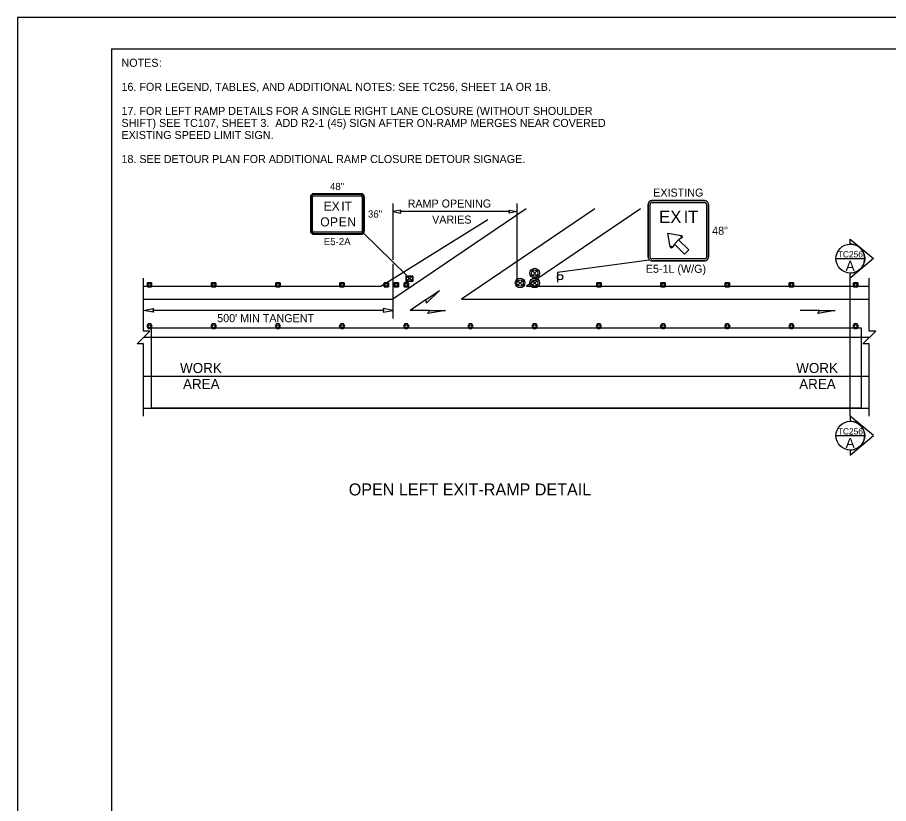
# Model space of a CAD drawing. Extents: x 99999 to 100116, y 99995 to 100013.
# Drawn here: x 100079.06 to 100087.75, y 100002.85 to 100010.69 of the extents above; entities that cross this region are included whole.
import ezdxf

# ---------------------------------------------------------------- set-up
doc = ezdxf.new("R2010")
doc.units = 0
for name, color, linetype in [('RD_MK_LineEdgeYellow', 7, 'Continuous'), ('RD_MK_LineLane', 7, 'Continuous'), ('SH_DE_DetailHeading2Text', 7, 'Continuous'), ('SH_GI_GeneralNotesBodyText', 7, 'Continuous'), ('SH_GI_PlotLimits', 7, 'Continuous'), ('SH_GI_SectionCut', 7, 'Continuous'), ('SH_GI_SheetBorder', 7, 'Continuous'), ('TR_SN_ConstructionSigns', 7, 'Continuous'), ('TR_WZ_PortableSignMount5ftMinBlk-Org', 7, 'Continuous'), ('TR_WZ_TallChanDevice', 7, 'Continuous'), ('TR_WZ_TrafficCone', 7, 'Continuous'), ('TR_WZ_TrafficSafetyDrum', 7, 'Continuous'), ('TR_WZ_WorkAreaLabel', 7, 'Continuous'), ('TR_WZ_WorkZoneDetails', 7, 'Continuous'), ('TR_WZ_WorkZoneTextCurrent', 7, 'Continuous')]:
    doc.layers.add(name, color=color, linetype=linetype)

msp = doc.modelspace()

# ---------------------------------------------------------------- linework, layer by layer
at = {"layer": 'RD_MK_LineEdgeYellow'}
for p, q in [((100084.1333, 100008.7784), (100082.8064, 100007.8789)), ((100080.32, 100007.8789), (100082.8064, 100007.8789)), ((100084.1377, 100007.8789), (100087.555, 100007.8789)), ((100080.32, 100007.1109), (100087.555, 100007.1109))]:
    msp.add_line(p, q, dxfattribs=at)
at = {"layer": 'RD_MK_LineLane'}
msp.add_lwpolyline([(100087.555, 100007.4949), (100080.32, 100007.4949)], dxfattribs=at)
at = {"layer": 'SH_GI_PlotLimits'}
msp.add_lwpolyline([(100079.0625, 99999.6875), (100096.0625, 99999.6875), (100096.0625, 100010.6875), (100079.0625, 100010.6875)], close=True, dxfattribs=at)
at = {"layer": 'SH_GI_SectionCut'}
for p, q in [((100087.3657, 100008.4258), (100087.3657, 100008.4767)), ((100087.3657, 100008.4767), (100087.5983, 100008.2818)), ((100087.5983, 100008.2818), (100087.3657, 100008.0869)), ((100087.3657, 100008.0869), (100087.3657, 100008.1378)), ((100087.3657, 100006.7109), (100087.3657, 100008.0869)), ((100087.3657, 100006.7109), (100087.3657, 100006.66)), ((100087.5983, 100006.516), (100087.3657, 100006.7109)), ((100087.3657, 100006.3211), (100087.5983, 100006.516)), ((100087.3657, 100006.372), (100087.3657, 100006.3211))]:
    msp.add_line(p, q, dxfattribs=at)
for points in [[(100087.2217, 100008.2818), (100087.5097, 100008.2818)], [(100087.2217, 100006.516), (100087.5097, 100006.516)]]:
    msp.add_lwpolyline(points, dxfattribs=at)
for centre in [(100087.3657, 100008.2818), (100087.3657, 100006.516)]:
    msp.add_circle(centre, 0.144, dxfattribs=at)
for centre in [(100087.3657, 100008.2818), (100087.3657, 100006.516)]:
    msp.add_arc(centre, 0.144, 269.99779, 90.00221, dxfattribs=at)
at = {"layer": 'SH_GI_SheetBorder'}
for q in [(100080, 100000), (100095.75, 100010.375)]:
    msp.add_line((100080, 100010.375), q, dxfattribs=at)
at = {"layer": 'TR_SN_ConstructionSigns'}
for p, q in [((100081.983, 100008.8955), (100081.983, 100008.558)), ((100081.9914, 100008.8955), (100081.9914, 100008.558)), ((100082.0055, 100008.558), (100082.0055, 100008.8955)), ((100082.4893, 100008.9292), (100082.0168, 100008.9292)), ((100082.4893, 100008.9208), (100082.0168, 100008.9208)), ((100082.0168, 100008.9067), (100082.4893, 100008.9067)), ((100082.5005, 100008.8955), (100082.5005, 100008.558)), ((100082.5146, 100008.558), (100082.5146, 100008.8955)), ((100082.523, 100008.558), (100082.523, 100008.8955)), ((100085.3881, 100008.8603), (100085.9131, 100008.8603)), ((100085.9131, 100008.8603), (100085.3881, 100008.8603)), ((100085.9131, 100008.8603), (100085.3881, 100008.8603)), ((100085.9131, 100008.8603), (100085.3881, 100008.8603)), ((100085.9131, 100008.8603), (100085.3881, 100008.8603)), ((100085.9131, 100008.8603), (100085.9131, 100008.8603)), ((100085.3506, 100008.2978), (100085.3506, 100008.8228)), ((100085.3506, 100008.8228), (100085.3506, 100008.8228)), ((100085.3506, 100008.8228), (100085.3506, 100008.2978)), ((100085.3506, 100008.8228), (100085.3506, 100008.2978)), ((100085.3506, 100008.8228), (100085.3506, 100008.2978)), ((100085.3506, 100008.8228), (100085.3506, 100008.2978)), ((100085.3693, 100008.2978), (100085.3693, 100008.8228)), ((100085.3881, 100008.8416), (100085.9131, 100008.8416)), ((100085.9318, 100008.8228), (100085.9318, 100008.2978)), ((100085.9506, 100008.8228), (100085.9506, 100008.2978)), ((100085.9506, 100008.2978), (100085.9506, 100008.8228)), ((100085.9506, 100008.2978), (100085.9506, 100008.8228)), ((100085.9506, 100008.2978), (100085.9506, 100008.8228)), ((100085.9506, 100008.2978), (100085.9506, 100008.8228)), ((100082.4893, 100008.5467), (100082.0168, 100008.5467)), ((100082.0168, 100008.5327), (100082.4893, 100008.5327)), ((100082.0168, 100008.5242), (100082.4893, 100008.5242)), ((100085.5462, 100008.5358), (100085.6821, 100008.511)), ((100085.571, 100008.3999), (100085.5462, 100008.5358)), ((100085.6821, 100008.511), (100085.6793, 100008.4988)), ((100085.6793, 100008.4988), (100085.6821, 100008.511)), ((100085.6793, 100008.4988), (100085.6857, 100008.4881)), ((100085.6857, 100008.4881), (100085.6793, 100008.4988)), ((100085.6125, 100008.4275), (100085.5939, 100008.3963)), ((100085.6125, 100008.4275), (100085.6544, 100008.4695)), ((100085.6544, 100008.4695), (100085.6125, 100008.4275)), ((100085.713, 100008.327), (100085.6125, 100008.4275)), ((100085.6857, 100008.4881), (100085.6544, 100008.4695)), ((100085.6544, 100008.4695), (100085.755, 100008.369)), ((100085.5832, 100008.4027), (100085.571, 100008.3999)), ((100085.571, 100008.3999), (100085.5832, 100008.4027)), ((100085.5939, 100008.3963), (100085.5832, 100008.4027)), ((100085.5832, 100008.4027), (100085.5939, 100008.3963)), ((100085.755, 100008.369), (100085.713, 100008.327)), ((100085.9131, 100008.2791), (100085.3881, 100008.2791)), ((100085.9131, 100008.2603), (100085.3881, 100008.2603)), ((100085.3881, 100008.2603), (100085.3881, 100008.2603)), ((100085.3881, 100008.2603), (100085.9131, 100008.2603)), ((100085.3881, 100008.2603), (100085.9131, 100008.2603)), ((100085.3881, 100008.2603), (100085.9131, 100008.2603)), ((100085.9506, 100008.2978), (100085.9506, 100008.2978))]:
    msp.add_line(p, q, dxfattribs=at)
for points in [[(100085.3881, 100008.2603), (100085.3881, 100008.2603)], [(100085.3881, 100008.2603), (100085.9131, 100008.2603), (100085.9131, 100008.2603)]]:
    msp.add_lwpolyline(points, dxfattribs=at)
for centre, radius, start, end in [((100082.0168, 100008.8955), 0.0338, 90, 180), ((100082.0168, 100008.8955), 0.0253, 90, 180.00001), ((100082.0168, 100008.8955), 0.0112, 90, 180.00001), ((100082.4893, 100008.8955), 0.0338, 360, 90), ((100082.4893, 100008.8955), 0.0253, 360, 90), ((100082.4893, 100008.8955), 0.0112, 360, 90), ((100085.3881, 100008.8228), 0.0375, 90, 180.00001), ((100085.3881, 100008.8228), 0.0375, 90, 180), ((100085.3881, 100008.8228), 0.0375, 90, 180), ((100085.3881, 100008.8228), 0.0375, 90, 180), ((100085.3881, 100008.8228), 0.0375, 90, 180), ((100085.9131, 100008.8228), 0.0375, 0, 90), ((100085.9131, 100008.8228), 0.0375, 0, 90), ((100085.9131, 100008.8228), 0.0375, 0, 90), ((100085.9131, 100008.8228), 0.0375, 0, 90), ((100085.9131, 100008.8228), 0.0375, 0, 90), ((100085.3881, 100008.8228), 0.0187, 90, 180.00001), ((100085.9131, 100008.8228), 0.0187, 0, 90), ((100082.0168, 100008.558), 0.0338, 180, 270.00001), ((100082.0168, 100008.558), 0.0253, 180.00001, 270), ((100082.0168, 100008.558), 0.0112, 180.00001, 270), ((100082.4893, 100008.558), 0.0338, 270.00001, 0.00001), ((100082.4893, 100008.558), 0.0253, 270, 0.00001), ((100082.4893, 100008.558), 0.0112, 270, 0.00001), ((100085.6793, 100008.4988), 0.0125, 300.67412, 77.22876), ((100085.5832, 100008.4027), 0.0125, 192.77123, 329.32586), ((100085.3881, 100008.2978), 0.0375, 180.00001, 270), ((100085.3881, 100008.2978), 0.0375, 180, 270.00001), ((100085.3881, 100008.2978), 0.0375, 180, 270.00001), ((100085.3881, 100008.2978), 0.0375, 180, 270), ((100085.3881, 100008.2978), 0.0375, 180, 270.00001), ((100085.3881, 100008.2978), 0.0187, 180.00001, 270), ((100085.9131, 100008.2978), 0.0375, 270, 0.00001), ((100085.9131, 100008.2978), 0.0375, 270.00001, 0.00001), ((100085.9131, 100008.2978), 0.0375, 270.00001, 0.00001), ((100085.9131, 100008.2978), 0.0375, 270.00001, 0.00001), ((100085.9131, 100008.2978), 0.0187, 270, 0.00001), ((100085.9131, 100008.2978), 0.0375, 270.00001, 0.00001)]:
    msp.add_arc(centre, radius, start, end, dxfattribs=at)
at = {"layer": 'TR_WZ_PortableSignMount5ftMinBlk-Org'}
for p, q in [((100082.9389, 100008.0416), (100082.9389, 100008.1216)), ((100083.0056, 100008.1076), (100082.9389, 100008.0556)), ((100083.0056, 100008.0556), (100082.9389, 100008.1076)), ((100082.9723, 100008.0816), (100082.9723, 100008.0816)), ((100082.9724, 100008.0816), (100082.9724, 100008.0816))]:
    msp.add_line(p, q, dxfattribs=at)
for points in [[(100083.0056, 100008.1076), (100083.0056, 100008.0556), (100082.9389, 100008.0556), (100082.9389, 100008.1076)], [(100082.9389, 100008.0556), (100083.0056, 100008.0556), (100083.0056, 100008.1076), (100082.9389, 100008.1076)]]:
    msp.add_lwpolyline(points, close=True, dxfattribs=at)
at = {"layer": 'TR_WZ_TallChanDevice'}
for points in [[(100080.3928, 100007.6319), (100080.3651, 100007.6319), (100080.3512, 100007.6079), (100080.3651, 100007.5839), (100080.3928, 100007.5839), (100080.4066, 100007.6079)], [(100081.0328, 100007.6319), (100081.0051, 100007.6319), (100080.9912, 100007.6079), (100081.0051, 100007.5839), (100081.0328, 100007.5839), (100081.0466, 100007.6079)], [(100081.6728, 100007.6319), (100081.6451, 100007.6319), (100081.6312, 100007.6079), (100081.6451, 100007.5839), (100081.6728, 100007.5839), (100081.6866, 100007.6079)], [(100082.3128, 100007.6319), (100082.2851, 100007.6319), (100082.2712, 100007.6079), (100082.2851, 100007.5839), (100082.3128, 100007.5839), (100082.3266, 100007.6079)], [(100082.9528, 100007.6319), (100082.9251, 100007.6319), (100082.9112, 100007.6079), (100082.9251, 100007.5839), (100082.9528, 100007.5839), (100082.9666, 100007.6079)], [(100083.5928, 100007.6319), (100083.5651, 100007.6319), (100083.5512, 100007.6079), (100083.5651, 100007.5839), (100083.5928, 100007.5839), (100083.6066, 100007.6079)], [(100084.2328, 100007.6319), (100084.2051, 100007.6319), (100084.1912, 100007.6079), (100084.2051, 100007.5839), (100084.2328, 100007.5839), (100084.2466, 100007.6079)], [(100084.8728, 100007.6319), (100084.8451, 100007.6319), (100084.8312, 100007.6079), (100084.8451, 100007.5839), (100084.8728, 100007.5839), (100084.8866, 100007.6079)], [(100085.5128, 100007.6319), (100085.4851, 100007.6319), (100085.4712, 100007.6079), (100085.4851, 100007.5839), (100085.5128, 100007.5839), (100085.5266, 100007.6079)], [(100086.1528, 100007.6319), (100086.1251, 100007.6319), (100086.1112, 100007.6079), (100086.1251, 100007.5839), (100086.1528, 100007.5839), (100086.1666, 100007.6079)], [(100086.7928, 100007.6319), (100086.7651, 100007.6319), (100086.7512, 100007.6079), (100086.7651, 100007.5839), (100086.7928, 100007.5839), (100086.8066, 100007.6079)], [(100087.4328, 100007.6319), (100087.4051, 100007.6319), (100087.3912, 100007.6079), (100087.4051, 100007.5839), (100087.4328, 100007.5839), (100087.4466, 100007.6079)]]:
    msp.add_lwpolyline(points, close=True, dxfattribs=at)
for points in [[(100080.3928, 100007.6319), (100080.3651, 100007.6319), (100080.3512, 100007.6079), (100080.3651, 100007.5839), (100080.3928, 100007.5839), (100080.4066, 100007.6079), (100080.3928, 100007.6319)], [(100081.0328, 100007.6319), (100081.0051, 100007.6319), (100080.9912, 100007.6079), (100081.0051, 100007.5839), (100081.0328, 100007.5839), (100081.0466, 100007.6079), (100081.0328, 100007.6319)], [(100081.6728, 100007.6319), (100081.6451, 100007.6319), (100081.6312, 100007.6079), (100081.6451, 100007.5839), (100081.6728, 100007.5839), (100081.6866, 100007.6079), (100081.6728, 100007.6319)], [(100082.3128, 100007.6319), (100082.2851, 100007.6319), (100082.2712, 100007.6079), (100082.2851, 100007.5839), (100082.3128, 100007.5839), (100082.3266, 100007.6079), (100082.3128, 100007.6319)], [(100082.9528, 100007.6319), (100082.9251, 100007.6319), (100082.9112, 100007.6079), (100082.9251, 100007.5839), (100082.9528, 100007.5839), (100082.9666, 100007.6079), (100082.9528, 100007.6319)], [(100083.5928, 100007.6319), (100083.5651, 100007.6319), (100083.5512, 100007.6079), (100083.5651, 100007.5839), (100083.5928, 100007.5839), (100083.6066, 100007.6079), (100083.5928, 100007.6319)], [(100084.2328, 100007.6319), (100084.2051, 100007.6319), (100084.1912, 100007.6079), (100084.2051, 100007.5839), (100084.2328, 100007.5839), (100084.2466, 100007.6079), (100084.2328, 100007.6319)], [(100084.8728, 100007.6319), (100084.8451, 100007.6319), (100084.8312, 100007.6079), (100084.8451, 100007.5839), (100084.8728, 100007.5839), (100084.8866, 100007.6079), (100084.8728, 100007.6319)], [(100085.5128, 100007.6319), (100085.4851, 100007.6319), (100085.4712, 100007.6079), (100085.4851, 100007.5839), (100085.5128, 100007.5839), (100085.5266, 100007.6079), (100085.5128, 100007.6319)], [(100086.1528, 100007.6319), (100086.1251, 100007.6319), (100086.1112, 100007.6079), (100086.1251, 100007.5839), (100086.1528, 100007.5839), (100086.1666, 100007.6079), (100086.1528, 100007.6319)], [(100086.7928, 100007.6319), (100086.7651, 100007.6319), (100086.7512, 100007.6079), (100086.7651, 100007.5839), (100086.7928, 100007.5839), (100086.8066, 100007.6079), (100086.7928, 100007.6319)], [(100087.4328, 100007.6319), (100087.4051, 100007.6319), (100087.3912, 100007.6079), (100087.4051, 100007.5839), (100087.4328, 100007.5839), (100087.4466, 100007.6079), (100087.4328, 100007.6319)]]:
    msp.add_lwpolyline(points, dxfattribs=at)
for centre in [(100080.3789, 100007.6079), (100081.0189, 100007.6079), (100081.6589, 100007.6079), (100082.2989, 100007.6079), (100082.9389, 100007.6079), (100083.5789, 100007.6079), (100084.2189, 100007.6079), (100084.8589, 100007.6079), (100085.4989, 100007.6079), (100086.1389, 100007.6079), (100086.7789, 100007.6079), (100087.4189, 100007.6079)]:
    msp.add_circle(centre, 0.015, dxfattribs=at)
at = {"layer": 'TR_WZ_TrafficCone'}
for points in [[(100080.3576, 100007.9989), (100080.4003, 100007.9989), (100080.4003, 100008.0416), (100080.3576, 100008.0416), (100080.3576, 100007.9989)], [(100080.3576, 100008.0416), (100080.4003, 100008.0416), (100080.4003, 100007.9989), (100080.3576, 100007.9989), (100080.3576, 100008.0416)], [(100080.9976, 100007.9989), (100081.0403, 100007.9989), (100081.0403, 100008.0416), (100080.9976, 100008.0416), (100080.9976, 100007.9989)], [(100080.9976, 100008.0416), (100081.0403, 100008.0416), (100081.0403, 100007.9989), (100080.9976, 100007.9989), (100080.9976, 100008.0416)], [(100081.6376, 100007.9989), (100081.6803, 100007.9989), (100081.6803, 100008.0416), (100081.6376, 100008.0416), (100081.6376, 100007.9989)], [(100081.6376, 100008.0416), (100081.6803, 100008.0416), (100081.6803, 100007.9989), (100081.6376, 100007.9989), (100081.6376, 100008.0416)], [(100082.2776, 100007.9989), (100082.3203, 100007.9989), (100082.3203, 100008.0416), (100082.2776, 100008.0416), (100082.2776, 100007.9989)], [(100082.2776, 100008.0416), (100082.3203, 100008.0416), (100082.3203, 100007.9989), (100082.2776, 100007.9989), (100082.2776, 100008.0416)], [(100082.7176, 100007.9989), (100082.7603, 100007.9989), (100082.7603, 100008.0416), (100082.7176, 100008.0416), (100082.7176, 100007.9989)], [(100082.7176, 100008.0416), (100082.7603, 100008.0416), (100082.7603, 100007.9989), (100082.7176, 100007.9989), (100082.7176, 100008.0416)], [(100082.8176, 100007.9989), (100082.8603, 100007.9989), (100082.8603, 100008.0416), (100082.8176, 100008.0416), (100082.8176, 100007.9989)], [(100082.8176, 100008.0416), (100082.8603, 100008.0416), (100082.8603, 100007.9989), (100082.8176, 100007.9989), (100082.8176, 100008.0416)], [(100082.9176, 100007.9989), (100082.9603, 100007.9989), (100082.9603, 100008.0416), (100082.9176, 100008.0416), (100082.9176, 100007.9989)], [(100082.9176, 100008.0416), (100082.9603, 100008.0416), (100082.9603, 100007.9989), (100082.9176, 100007.9989), (100082.9176, 100008.0416)], [(100084.8376, 100007.9989), (100084.8803, 100007.9989), (100084.8803, 100008.0416), (100084.8376, 100008.0416), (100084.8376, 100007.9989)], [(100084.8376, 100008.0416), (100084.8803, 100008.0416), (100084.8803, 100007.9989), (100084.8376, 100007.9989), (100084.8376, 100008.0416)], [(100085.4776, 100007.9989), (100085.5203, 100007.9989), (100085.5203, 100008.0416), (100085.4776, 100008.0416), (100085.4776, 100007.9989)], [(100085.4776, 100008.0416), (100085.5203, 100008.0416), (100085.5203, 100007.9989), (100085.4776, 100007.9989), (100085.4776, 100008.0416)], [(100086.1176, 100007.9989), (100086.1603, 100007.9989), (100086.1603, 100008.0416), (100086.1176, 100008.0416), (100086.1176, 100007.9989)], [(100086.1176, 100008.0416), (100086.1603, 100008.0416), (100086.1603, 100007.9989), (100086.1176, 100007.9989), (100086.1176, 100008.0416)], [(100086.7576, 100007.9989), (100086.8003, 100007.9989), (100086.8003, 100008.0416), (100086.7576, 100008.0416), (100086.7576, 100007.9989)], [(100086.7576, 100008.0416), (100086.8003, 100008.0416), (100086.8003, 100007.9989), (100086.7576, 100007.9989), (100086.7576, 100008.0416)], [(100087.3976, 100007.9989), (100087.4403, 100007.9989), (100087.4403, 100008.0416), (100087.3976, 100008.0416), (100087.3976, 100007.9989)], [(100087.3976, 100008.0416), (100087.4403, 100008.0416), (100087.4403, 100007.9989), (100087.3976, 100007.9989), (100087.3976, 100008.0416)]]:
    msp.add_lwpolyline(points, dxfattribs=at)
for centre in [(100080.3789, 100008.0202), (100081.0189, 100008.0202), (100081.6589, 100008.0202), (100082.2989, 100008.0202), (100082.7389, 100008.0202), (100082.8389, 100008.0202), (100082.9389, 100008.0202), (100084.8589, 100008.0202), (100085.4989, 100008.0202), (100086.1389, 100008.0202), (100086.7789, 100008.0202), (100087.4189, 100008.0202)]:
    msp.add_circle(centre, 0.0133, dxfattribs=at)
at = {"layer": 'TR_WZ_TrafficSafetyDrum'}
for p, q in [((100084.1963, 100008.1598), (100084.2415, 100008.1146)), ((100084.2415, 100008.1598), (100084.1963, 100008.1146)), ((100084.0513, 100008.0615), (100084.0965, 100008.0163)), ((100084.0965, 100008.0615), (100084.0513, 100008.0163)), ((100084.1963, 100008.0615), (100084.2415, 100008.0163)), ((100084.2415, 100008.0615), (100084.1963, 100008.0163))]:
    msp.add_line(p, q, dxfattribs=at)
for centre, radius in [((100084.2189, 100008.1372), 0.048), ((100084.2189, 100008.1372), 0.048), ((100084.2189, 100008.1372), 0.032), ((100084.0739, 100008.0389), 0.048), ((100084.0739, 100008.0389), 0.048), ((100084.0739, 100008.0389), 0.032), ((100084.2189, 100008.0389), 0.048), ((100084.2189, 100008.0389), 0.048), ((100084.2189, 100008.0389), 0.032)]:
    msp.add_circle(centre, radius, dxfattribs=at)
at = {"layer": 'TR_WZ_WorkZoneDetails'}
for p, q in [((100082.8064, 100008.8313), (100082.8064, 100008.27)), ((100084.8178, 100008.7784), (100083.9935, 100008.2196)), ((100084.0419, 100008.8313), (100084.0419, 100008.0389)), ((100085.2753, 100008.7784), (100084.1377, 100008.0069)), ((100082.6847, 100008.0069), (100083.7508, 100008.6713)), ((100083.9669, 100008.7513), (100082.8814, 100008.7513)), ((100082.9389, 100008.1216), (100082.5131, 100008.5341)), ((100084.4451, 100008.1469), (100085.3616, 100008.2713)), ((100082.8064, 100008.23), (100082.8064, 100007.6859)), ((100083.9935, 100008.2196), (100083.4908, 100007.8789)), ((100084.4451, 100008.1469), (100084.4451, 100008.0469)), ((100080.32, 100008.0069), (100082.6847, 100008.0069)), ((100084.1377, 100008.0069), (100087.555, 100008.0069)), ((100083.1385, 100007.8741), (100082.9788, 100007.7659)), ((100083.4908, 100007.8789), (100084.1377, 100007.8789)), ((100082.7126, 100007.7659), (100080.4137, 100007.7659)), ((100083.1717, 100007.7659), (100082.9788, 100007.7659)), ((100087.0586, 100007.7659), (100086.8658, 100007.7659)), ((100080.32, 100006.7909), (100087.555, 100006.7909))]:
    msp.add_line(p, q, dxfattribs=at)
for points in [[(100082.8064, 100008.7513), (100082.885, 100008.7359), (100082.8814, 100008.7513), (100082.885, 100008.7667)], [(100084.0419, 100008.7513), (100083.9633, 100008.7359), (100083.9669, 100008.7513), (100083.9633, 100008.7667)], [(100083.2686, 100007.9623), (100083.1411, 100007.8385), (100083.1385, 100007.8741)], [(100080.32, 100007.7659), (100080.4183, 100007.7851), (100080.4137, 100007.7659), (100080.4183, 100007.7466)], [(100082.8063, 100007.7659), (100082.7081, 100007.7851), (100082.7126, 100007.7659), (100082.7081, 100007.7466)], [(100083.3289, 100007.7659), (100083.1539, 100007.735), (100083.1717, 100007.7659)], [(100087.2159, 100007.7659), (100087.0408, 100007.735), (100087.0586, 100007.7659)], [(100080.4, 100006.7909), (100080.4, 100007.5909), (100087.475, 100007.5909), (100087.475, 100006.7909)]]:
    msp.add_lwpolyline(points, close=True, dxfattribs=at)
for points in [[(100080.32, 100006.7109), (100080.32, 100007.433), (100080.256, 100007.433), (100080.384, 100007.5569), (100080.32, 100007.5569), (100080.32, 100008.0869)], [(100087.555, 100006.7109), (100087.555, 100007.433), (100087.491, 100007.433), (100087.619, 100007.5569), (100087.555, 100007.5569), (100087.555, 100008.0869)]]:
    msp.add_lwpolyline(points, dxfattribs=at)
msp.add_circle((100084.4721, 100008.0968), 0.027, dxfattribs=at)
msp.add_circle((100084.4721, 100008.0968), 0.027, dxfattribs=at)

# ---------------------------------------------------------------- texts
at = {"layer": 'SH_DE_DetailHeading2Text'}
msp.add_text('OPEN LEFT EXIT-RAMP DETAIL', height=0.12, rotation=360, dxfattribs=at).set_placement((100082.3657, 100005.9196))
at = {"layer": 'SH_GI_GeneralNotesBodyText'}
for s, p in [('NOTES', (100080.1, 100010.195)), (':', (100080.4743, 100010.195)), ('16. FOR LEGEND, TABLES, AND ADDITIONAL NOTES: SEE TC256, SHEET 1A OR 1B.', (100080.1, 100009.955)), ('17. FOR LEFT RAMP DETAILS FOR A SINGLE RIGHT LANE CLOSURE (WITHOUT SHOULDER ', (100080.1, 100009.715)), ('SHIFT) SEE TC107, SHEET 3.  ADD R2-1 (45) SIGN AFTER ON-RAMP MERGES NEAR COVERED ', (100080.1, 100009.595)), ('EXISTING SPEED LIMIT SIGN.', (100080.1, 100009.475)), ('18. SEE DETOUR PLAN FOR ADDITIONAL RAMP CLOSURE DETOUR SIGNAGE.', (100080.1, 100009.235))]:
    msp.add_text(s, height=0.08, rotation=360, dxfattribs=at).set_placement(p)
at = {"layer": 'SH_GI_SectionCut'}
for p in [(100087.2408, 100008.2934), (100087.2408, 100006.5276)]:
    msp.add_text('TC256', height=0.0625, dxfattribs=at).set_placement(p)
for p in [(100087.3195, 100008.1598), (100087.3195, 100006.394)]:
    msp.add_text('A', height=0.1, rotation=359.99005, dxfattribs=at).set_placement(p)
at = {"layer": 'TR_SN_ConstructionSigns'}
for s, height, p in [('48"', 0.072, (100082.1782, 100008.9652)), ('EXISTING', 0.08, (100085.4008, 100008.9003)), ('E', 0.09, (100082.1153, 100008.7605)), ('X', 0.09, (100082.1954, 100008.7605)), ('I', 0.09, (100082.2917, 100008.7605)), ('T', 0.09, (100082.3232, 100008.7605)), ('36"', 0.072, (100082.5568, 100008.6907)), ('O', 0.09, (100082.0816, 100008.603)), ('P', 0.09, (100082.1779, 100008.603)), ('E', 0.09, (100082.2661, 100008.603)), ('N', 0.09, (100082.3516, 100008.603)), ('48"', 0.08, (100085.9882, 100008.5203)), ('E5-2A', 0.072, (100082.1164, 100008.4162)), ('E5-1L (W/G)', 0.08, (100085.327, 100008.1403))]:
    msp.add_text(s, height=height, rotation=360, dxfattribs=at).set_placement(p)
for s, p in [('E', (100085.4593, 100008.6358)), ('X', (100085.5706, 100008.6358)), ('I', (100085.7043, 100008.6358)), ('T', (100085.7481, 100008.6358))]:
    msp.add_text(s, height=0.125, dxfattribs=at).set_placement(p)
at = {"layer": 'TR_WZ_WorkAreaLabel'}
for s, p in [('WORK', (100080.684, 100007.1409)), ('WORK', (100086.8263, 100007.1409)), ('AREA', (100080.7137, 100006.9809)), ('AREA', (100086.8559, 100006.9809))]:
    msp.add_text(s, height=0.1, dxfattribs=at).set_placement(p)
at = {"layer": 'TR_WZ_WorkZoneTextCurrent'}
for s, p in [('RAMP OPENING', (100082.9527, 100008.7913)), ('VARIES', (100083.1965, 100008.6313)), ("500' MIN TANGENT", (100081.0542, 100007.6479))]:
    msp.add_text(s, height=0.08, dxfattribs=at).set_placement(p)

doc.saveas('drawing.dxf')
